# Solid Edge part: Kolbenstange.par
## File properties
Username: bmolnar
Dokumentum tartalom típus: 0
Author: bmolnar
Last saved by: bmolnar
Revision: 82
Sűrűség: 0,000 kg/m^3
Pontosság: 0,990
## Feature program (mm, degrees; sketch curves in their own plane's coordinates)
base feature "unnamed BaseFeature 1"
sketch for "unnamed Protrusion 1" plane through (0, 0, -11.1) normal (0, 0, -1) x-axis (1, 0, 0)
  circle centre (0, 0) radius 16
extrude "unnamed Protrusion 1" add finite 15.8 along +normal
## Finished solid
Body 1: solid body, 13 faces, 19 edges, 8 vertices.
  Faces by surface: plane 7, cylinder 3, cone 2, torus 1
  Edges by curve: circle 9, line 6, ellipse 2, intersection 2
Bounding box of the edges (mm; curved faces can reach further): 32.000 x 32.000 x 66.414, from (-16, -16, -26.9) to (16, 16, 39.5137).
Cylindrical faces by radius (mm): R3.3235 x1, R6 x1, R16 x1
Conical faces (half-angle, radius in mm at the cone's reference point): 45 deg R3.6735 x1, 59 deg R1.6618 x1
Toroidal faces (ring radius, tube radius in mm): R4.8 r1.2 x1
Planar faces by outward normal: +x 1, +z 2, -x 1, -z 1, oblique 2
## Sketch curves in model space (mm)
circle centre (0, 0, -11.1) radius 16
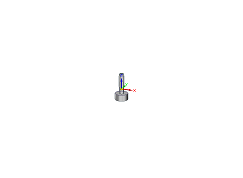
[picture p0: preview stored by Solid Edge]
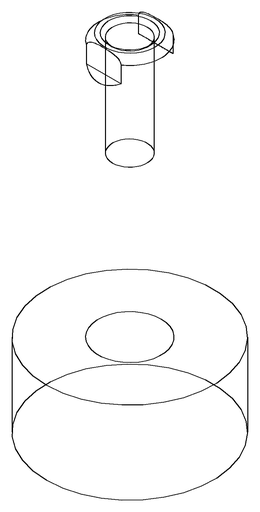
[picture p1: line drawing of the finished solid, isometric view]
